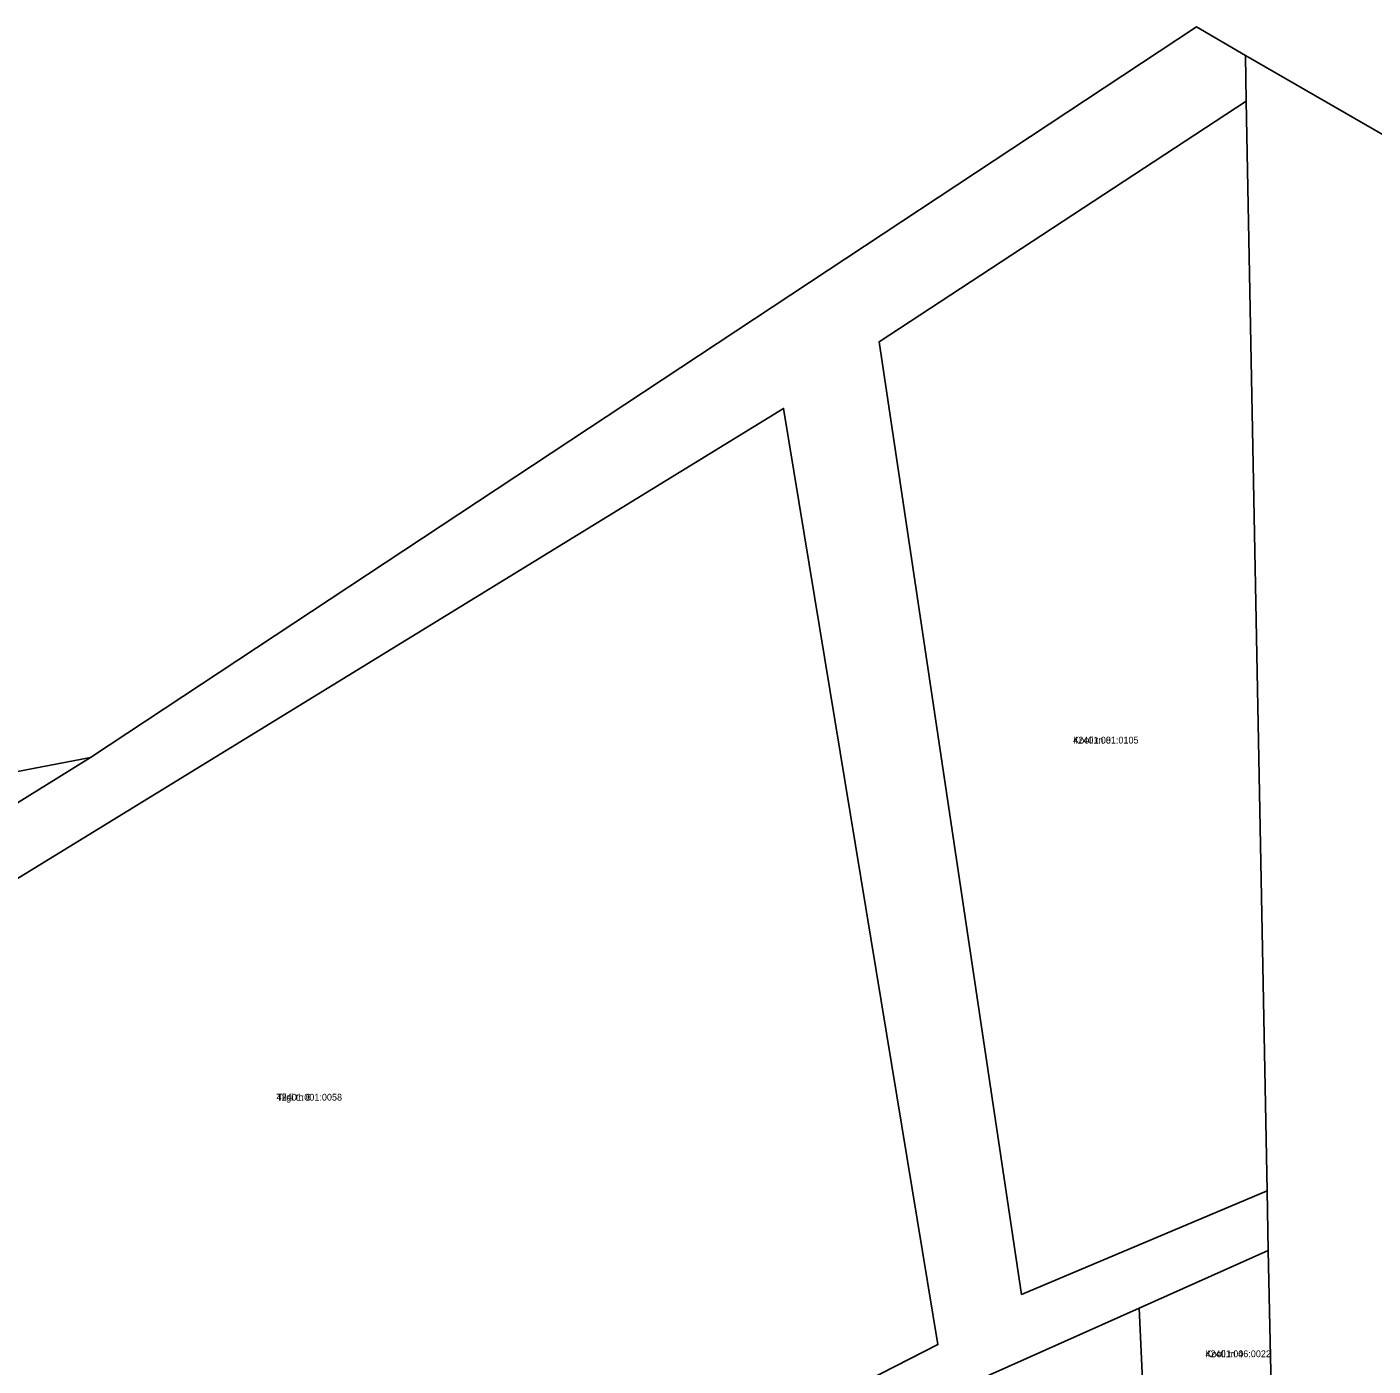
# Model space of a CAD drawing. Extents: x 595979 to 597983, y 6604231 to 6607350.
# Drawn here: x 597213 to 597511.5, y 6606896.1 to 6607193 of the extents above; entities that cross this region are included whole.
import ezdxf

# ---------------------------------------------------------------- set-up
doc = ezdxf.new("R2010")
doc.units = 0
for name, color, linetype in [('L_AADRESS', 7, 'Continuous'), ('PIIR', 7, 'Continuous'), ('TUNNUS', 7, 'Continuous')]:
    doc.layers.add(name, color=color, linetype=linetype)

msp = doc.modelspace()

# ---------------------------------------------------------------- linework, layer by layer
at = {"layer": 'PIIR'}
msp.add_lwpolyline([(597017.44, 6606900.77), (597227.14, 6607031), (597472.32, 6607193.03), (597483.18, 6607186.71), (597483.37, 6607176.6), (597401.98, 6607123.23), (597433.56, 6606911.97), (597488.02, 6606934.96), (597488.27, 6606921.71), (597459.63, 6606908.91), (597426.55, 6606894.12), (597414.73, 6606888.84), (597369.21, 6606868.49), (597372.57, 6606863.67), (597359.62, 6606857.46), (597351.95, 6606851.81), (597348.63, 6606856.37), (597331.97, 6606839.29), (597312.99, 6606819.9), (597309.9, 6606829.23), (597345.38, 6606865.19), (597415.02, 6606900.83), (597380.8, 6607108.42), (597047.73, 6606904.01)], dxfattribs=at)
for points in [[(597756.25, 6607029.31), (597555.1, 6606895.13), (597595.03, 6606781.37), (597596.23, 6606778.19), (597573.92, 6606775.05), (597536, 6606765.81), (597493.26, 6606758.6), (597491.45, 6606773.47), (597488.27, 6606921.71), (597488.02, 6606934.96), (597483.37, 6607176.6), (597483.18, 6607186.71)], [(597488.02, 6606934.96), (597433.56, 6606911.97), (597401.98, 6607123.23), (597483.37, 6607176.6)], [(597185.54, 6606803.62), (597168.46, 6606801.45), (597157.16, 6606852.69), (597127.58, 6606861.69), (597047.73, 6606904.01), (597380.8, 6607108.42), (597415.02, 6606900.83), (597345.38, 6606865.19), (597309.9, 6606829.23), (597300.15, 6606858.7), (597271.1, 6606844.74), (597243, 6606831.24), (597214.14, 6606817.36)], [(597227.14, 6607031), (597017.44, 6606900.77), (597021.47, 6607025.87), (597119.23, 6607010.32)], [(597488.27, 6606921.71), (597489.06, 6606884.73), (597461.14, 6606876.87), (597459.63, 6606908.91)], [(597459.63, 6606908.91), (597461.14, 6606876.87), (597430.24, 6606870.71), (597426.55, 6606894.12)]]:
    msp.add_lwpolyline(points, close=True, dxfattribs=at)

# ---------------------------------------------------------------- texts
at = {"layer": 'L_AADRESS'}
for s, p in [('Kooli tn 8', (597445, 6607034.12)), ('Tiigi tn 6', (597268.4, 6606954.94)), ('Kooli tn 4', (597474.35, 6606898.04))]:
    msp.add_text(s, height=1.5, dxfattribs=at).set_placement(p)
at = {"layer": 'TUNNUS'}
for s, p in [('42401:001:0105', (597445, 6607034.12)), ('42401:001:0058', (597268.4, 6606954.94)), ('42401:006:0022', (597474.35, 6606898.04))]:
    msp.add_text(s, height=1.5, dxfattribs=at).set_placement(p)

doc.saveas('drawing.dxf')
